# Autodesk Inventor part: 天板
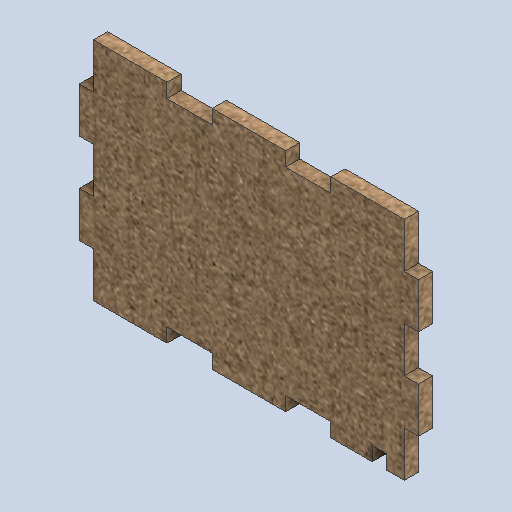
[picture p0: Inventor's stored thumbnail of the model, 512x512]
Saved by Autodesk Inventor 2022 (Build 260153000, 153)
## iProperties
Created: 2024-11
Part Number: 天板
Material: MDF 中密度繊維ボード
Document SubType Name: Modeling
Designer: shimizu
Density: 0.8 g/cm^3
Appearance: ダンボール - 段ボール紙
Author: shimizu
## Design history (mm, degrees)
sketch "スケッチ1"
  geometry: L1 (-25.119, 2.566)-(-27.619, 2.566); L2 (-27.619, 2.566)-(-27.619, -5.434); L3 (-27.619, -5.434)-(-25.119, -5.434); L4 (-25.119, -13.434)-(-27.619, -13.434); L5 (-27.619, -13.434)-(-27.619, -21.434); L6 (-27.619, -21.434)-(-25.119, -21.434); L7 (29.881, 2.566)-(32.381, 2.566); L8 (32.381, 2.566)-(32.381, -5.434); L9 (32.381, -5.434)-(29.881, -5.434); L10 (29.881, -13.434)-(32.381, -13.434); L11 (32.381, -13.434)-(32.381, -21.434); L12 (32.381, -21.434)-(29.881, -21.434); L13 (-25.119, 2.566)-(-25.119, 10.566); L14 (-25.119, -29.434)-(-25.119, -21.434); L15 (-25.119, -13.434)-(-25.119, -5.434); L16 (29.881, 10.566)-(29.881, 2.566); L17 (29.881, -5.434)-(29.881, -13.434); L18 (29.881, -21.434)-(29.881, -29.434); L19 (-4.119, -29.434)-(-4.119, -26.934); L20 (-4.119, -26.934)-(-12.119, -26.934); L21 (-12.119, -26.934)-(-12.119, -29.434); L22 (16.881, -29.434)-(16.881, -26.934); L23 (16.881, -26.934)-(8.881, -26.934); L24 (8.881, -26.934)-(8.881, -29.434); L25 (-4.119, 10.566)-(-4.119, 8.066); L26 (-4.119, 8.066)-(-12.119, 8.066); L27 (-12.119, 8.066)-(-12.119, 10.566); L28 (16.881, 10.566)-(16.881, 8.066); L29 (16.881, 8.066)-(8.881, 8.066); L30 (8.881, 8.066)-(8.881, 10.566); L31 (-25.119, 10.566)-(-12.119, 10.566); L32 (-4.119, 10.566)-(8.881, 10.566); L33 (16.881, 10.566)-(29.881, 10.566); L34 (-12.119, -29.434)-(-25.119, -29.434); L35 (29.881, -29.434)-(16.881, -29.434); L36 (8.881, -29.434)-(-4.119, -29.434); L37 (24.191, -29.434)-(26.701, -29.434); L38 (26.701, -29.434)-(26.701, -26.934); L39 (26.701, -26.934)-(24.191, -26.934); L40 (24.191, -26.934)-(24.191, -29.434); 2 further points
  constraints: 80 end point, 28 parallel, 14 perpendicular, 8 horizontal, 2 collinear, 1 point on line
  dimensions: "d29" = 55 distance between parallel lines of L17 L15; "d30" = 35 distance between parallel lines of L20 L26; "d31" = 60 distance between parallel lines of L11 L5; "d32" = 13 distance of L21.end L14.start; "d33" = 13 distance of L24.end L19.start; "d34" = 13 distance of L18.end L22.start; "d35" = 13 distance of L13.end L27.end; "d36" = 13 distance of L25.start L30.end; "d37" = 13 distance of L28.start L16.start; "d38" = 8 distance of L28.end L29.end; "d39" = 8 distance of L25.end L26.end; "d40" = 8 distance of L22.end L23.end; "d41" = 8 distance of L19.end L20.end; "d42" = 8 distance of L9.end L10.start; "d43" = 2.51 distance between parallel lines of L40 L38; "d44" = 2.5 distance between parallel lines of L37 L39; "d45" = 3.18 distance between parallel lines of L38 L18
extrude "押し出し1" new body sketch "スケッチ1" distance "d2" = 2.5; taper "d3" = 0 deg
node "ソリッド1"
